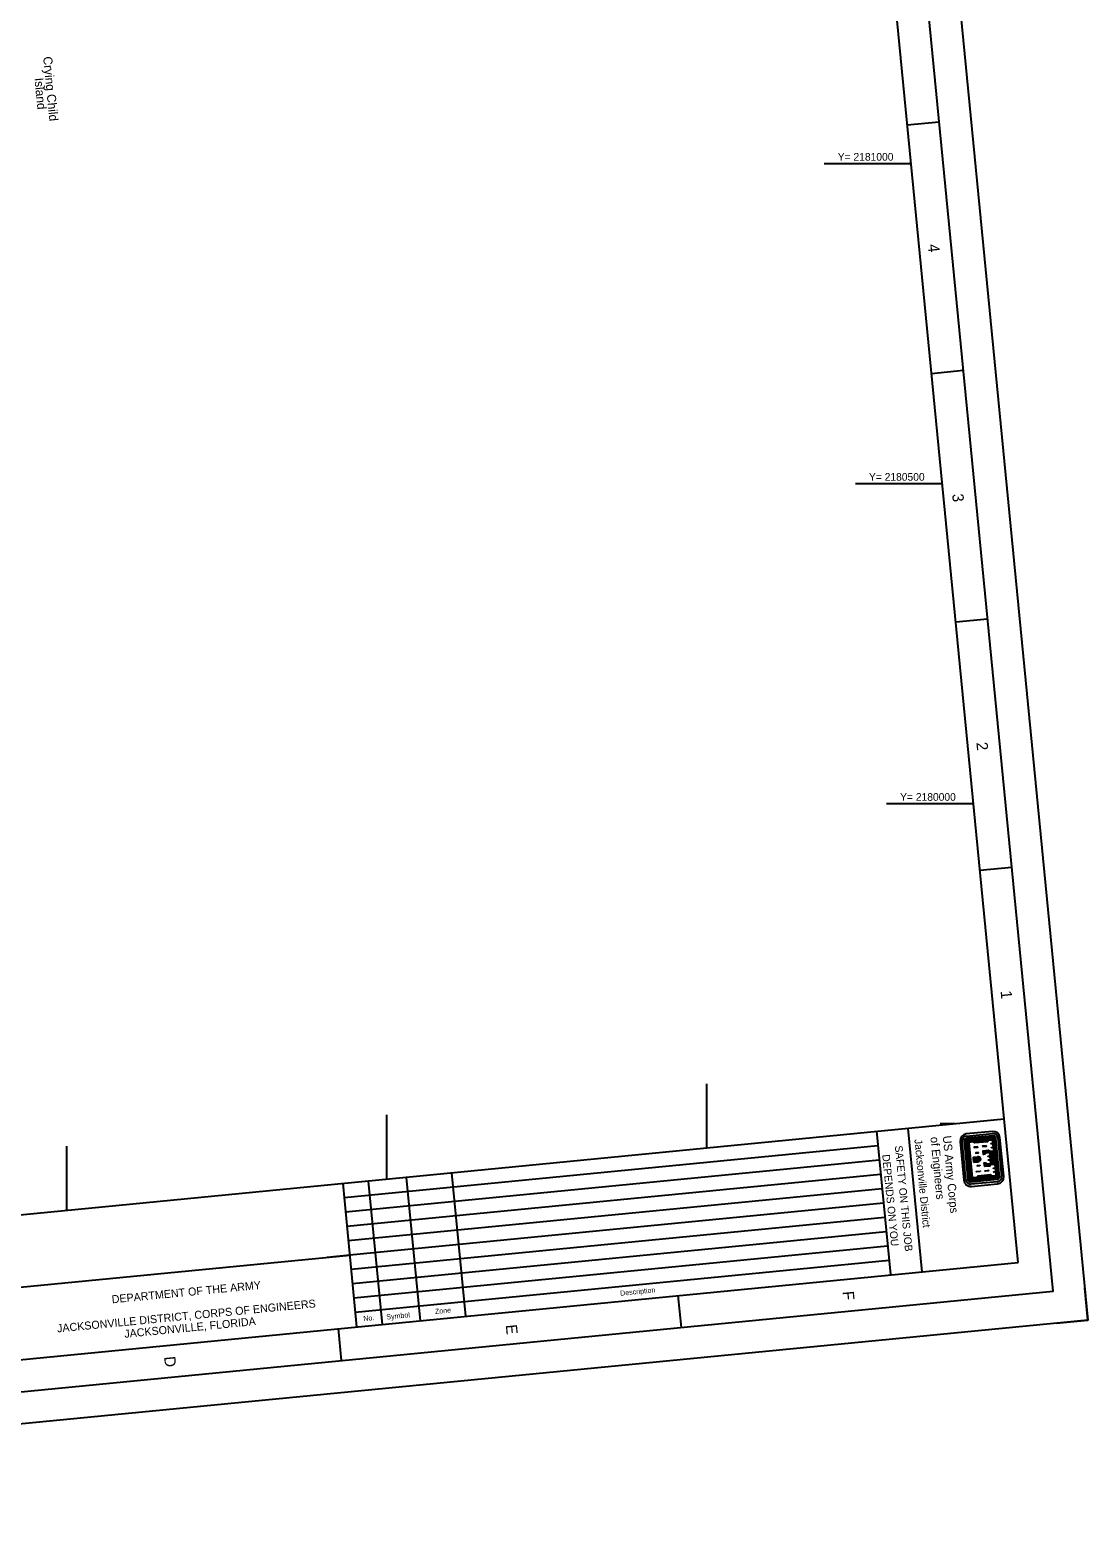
# Model space of a CAD drawing. Extents: x 516285 to 520096, y 2178864 to 2183573.
# Drawn here: x 518443 to 520096, y 2178864 to 2181209 of the extents above; entities that cross this region are included whole.
import ezdxf

# ---------------------------------------------------------------- set-up
doc = ezdxf.new("R2010")
doc.units = 0
for name, color, linetype in [('G-ANNO-NPLT', 7, 'Continuous'), ('G-ANNO-TEXT-LOGO', 7, 'Continuous'), ('G-ANNO-TEXT-TTLB', 7, 'Continuous'), ('G-ANNO-TTLB', 7, 'Continuous'), ('V-SITE-IDEN', 7, 'Continuous'), ('V-TOPO-COOR-STAT', 7, 'Continuous')]:
    doc.layers.add(name, color=color, linetype=linetype)

msp = doc.modelspace()

# ---------------------------------------------------------------- linework, layer by layer
at = {"layer": 'G-ANNO-NPLT'}
msp.add_lwpolyline([(519669, 2183572.9), (520095.6, 2179193.6), (516711.7, 2178864), (516285.1, 2183243.3)], close=True, dxfattribs=at)
msp.add_lwpolyline([(520045.9, 2179188.8), (520095.6, 2179193.6), (520090.8, 2179243.4)], dxfattribs=at)
at = {"layer": 'G-ANNO-TEXT-LOGO'}
for p, q in [((519895.8, 2179472.5), (519901.6, 2179412)), ((519904.9, 2179412.3), (519899, 2179472.8)), ((519908.4, 2179412.7), (519902.5, 2179473.2)), ((519909.2, 2179412.7), (519903.3, 2179473.3)), ((519910.1, 2179412.8), (519904.2, 2179473.3)), ((519911, 2179412.9), (519905.1, 2179473.4)), ((519946.3, 2179488.2), (519905.5, 2179484.2)), ((519905.8, 2179481), (519946.6, 2179485)), ((519911.8, 2179413), (519905.9, 2179473.5)), ((519946.9, 2179481.5), (519906.1, 2179477.6)), ((519947, 2179480.6), (519906.2, 2179476.7)), ((519947.1, 2179479.8), (519906.3, 2179475.9)), ((519947.2, 2179478.9), (519906.4, 2179475)), ((519947.3, 2179478), (519906.5, 2179474.1)), ((519947.3, 2179477.1), (519906.8, 2179473.2)), ((519912.7, 2179413.5), (519906.8, 2179473.2)), ((519947.4, 2179476.4), (519907.8, 2179472.5)), ((519913.5, 2179414.4), (519907.8, 2179472.5)), ((519938.8, 2179474.8), (519917.9, 2179472.8)), ((519938, 2179473.8), (519919, 2179472)), ((519953.8, 2179417.1), (519947.9, 2179477.6)), ((519954.7, 2179417.2), (519948.8, 2179477.7)), ((519955.5, 2179417.3), (519949.6, 2179477.8)), ((519956.4, 2179417.3), (519950.5, 2179477.9)), ((519957.3, 2179417.4), (519951.4, 2179477.9)), ((519954.8, 2179478.3), (519960.7, 2179417.8)), ((519963.9, 2179418.1), (519958, 2179478.6)), ((519916.1, 2179448), (519922.8, 2179448.6)), ((519916.1, 2179448), (519916.9, 2179440)), ((519916.2, 2179447.2), (519922.9, 2179447.8)), ((519916.3, 2179446.3), (519923, 2179446.9)), ((519944, 2179456), (519945.8, 2179437.5)), ((519944.9, 2179456.1), (519946.7, 2179437.6)), ((519945.7, 2179456.2), (519947.5, 2179437.7)), ((519946.6, 2179456.3), (519948.4, 2179437.8)), ((519947.5, 2179456.4), (519949.3, 2179437.8)), ((519948.3, 2179456.4), (519950.1, 2179437.9)), ((519949.2, 2179456.5), (519951, 2179438)), ((519916.4, 2179445.4), (519923.1, 2179446)), ((519916.5, 2179444.6), (519923.1, 2179445.2)), ((519916.6, 2179443.4), (519923.2, 2179444.1)), ((519916.7, 2179442.6), (519923.3, 2179443.3)), ((519916.7, 2179441.7), (519923.4, 2179442.4)), ((519916.8, 2179440.8), (519923.5, 2179441.5)), ((519916.9, 2179440), (519923.6, 2179440.7)), ((519953.3, 2179416.5), (519912.4, 2179412.6)), ((519953.3, 2179415.6), (519912.5, 2179411.7)), ((519953.4, 2179414.8), (519912.6, 2179410.9)), ((519953.2, 2179417.4), (519912.7, 2179413.5)), ((519953.5, 2179413.9), (519912.7, 2179410)), ((519953.6, 2179413.1), (519912.8, 2179409.1)), ((519953.9, 2179409.7), (519913.1, 2179405.7)), ((519913.4, 2179402.4), (519954.2, 2179406.4)), ((519953.1, 2179418.2), (519913.5, 2179414.4)), ((519944.3, 2179418.1), (519923.6, 2179416.1)), ((519943.4, 2179418.9), (519924.4, 2179417))]:
    msp.add_line(p, q, dxfattribs=at)
for points in [[(519947.5, 2179475.7), (519939.6, 2179474.9), (519938.1, 2179473), (519919.1, 2179471.2), (519917.1, 2179472.7), (519908.5, 2179471.9), (519914, 2179415.1), (519922.7, 2179416), (519924.3, 2179417.9), (519943.3, 2179419.8), (519945.2, 2179418.2), (519953, 2179418.9), (519952.3, 2179426.4), (519951.7, 2179432.2), (519951.2, 2179437.5), (519943.3, 2179436.8), (519941.8, 2179434.7), (519934.9, 2179434), (519934.5, 2179438.2), (519935.2, 2179438.3), (519937.1, 2179436.7), (519944.9, 2179437.4), (519944.2, 2179444.9), (519943.6, 2179450.7), (519943.1, 2179455.9), (519935.3, 2179455.2), (519933.7, 2179453.2), (519933, 2179453.1), (519932.6, 2179457.3), (519939.6, 2179458), (519941.4, 2179456.4), (519949.3, 2179457.1), (519948.6, 2179464.6), (519948, 2179470.4), (519947.5, 2179475.7)], [(519946.7, 2179474.8), (519940.1, 2179474.1), (519938.5, 2179472.2), (519918.8, 2179470.2), (519916.8, 2179471.9), (519909.5, 2179471.1), (519914.8, 2179416), (519922.2, 2179416.7), (519923.8, 2179418.8), (519943.5, 2179420.7), (519945.5, 2179419), (519952, 2179419.6), (519951.5, 2179425), (519948.4, 2179424.7), (519948.4, 2179425.2), (519951.5, 2179425.5), (519951, 2179430.8), (519947.9, 2179430.5), (519947.8, 2179430.9), (519950.9, 2179431.2), (519950.4, 2179436.6), (519943.8, 2179435.9), (519942.2, 2179433.9), (519934.2, 2179433.2), (519933.6, 2179438.9), (519935.5, 2179439.1), (519937.4, 2179437.5), (519944, 2179438.1), (519943.5, 2179443.5), (519940.4, 2179443.2), (519940.4, 2179443.6), (519943.5, 2179443.9), (519942.9, 2179449.3), (519939.8, 2179449), (519939.8, 2179449.5), (519942.9, 2179449.8), (519942.4, 2179455.1), (519935.8, 2179454.4), (519934.2, 2179452.5), (519932.3, 2179452.3), (519931.7, 2179458), (519939.8, 2179458.8), (519941.8, 2179457.2), (519948.3, 2179457.9), (519947.8, 2179463.1), (519944.7, 2179462.8), (519944.7, 2179463.3), (519947.8, 2179463.6), (519947.2, 2179469), (519944.2, 2179468.7), (519944.1, 2179469.1), (519947.2, 2179469.4), (519946.7, 2179474.8)], [(519923.6, 2179464.3), (519917.7, 2179463.7), (519917.8, 2179463.1), (519923.6, 2179463.7), (519923.6, 2179464.3)], [(519924.5, 2179455.1), (519920.4, 2179454.7), (519920.4, 2179454.2), (519924.5, 2179454.6), (519924.5, 2179455.1)], [(519936.8, 2179465.6), (519931, 2179465), (519931.1, 2179464.4), (519936.9, 2179465), (519936.8, 2179465.6)], [(519939.8, 2179456.6), (519939.3, 2179457.1), (519933.6, 2179456.5), (519933.8, 2179454.6), (519934.9, 2179456), (519939.9, 2179456.5)], [(519927.4, 2179425.6), (519921.5, 2179425), (519921.4, 2179425.5), (519927.3, 2179426.1), (519927.4, 2179425.6)], [(519926.5, 2179434.6), (519922.4, 2179434.2), (519922.3, 2179434.7), (519926.4, 2179435.1), (519926.5, 2179434.6)], [(519940.6, 2179426.9), (519934.8, 2179426.3), (519934.8, 2179426.8), (519940.5, 2179427.4), (519940.6, 2179426.9)], [(519941.8, 2179436.1), (519941.4, 2179435.6), (519935.7, 2179435), (519935.5, 2179436.8), (519936.9, 2179435.7), (519941.9, 2179436.2)]]:
    msp.add_lwpolyline(points, dxfattribs=at)
for centre, major_axis, start_param, end_param in [((519906.5, 2179473.5), (-1, 10.7), 6.28317, 7.853966), ((519906.5, 2179473.5), (-0.73, 7.45), 6.28317, 7.853966), ((519906.5, 2179473.5), (-0.39, 4), 6.28317, 7.853966), ((519906.5, 2179473.5), (-0.31, 3.13), 6.28317, 7.853966), ((519906.5, 2179473.5), (-0.22, 2.27), 6.28317, 7.853966), ((519906.5, 2179473.5), (-0.14, 1.41), 6.28317, 7.853966), ((519906.5, 2179473.5), (-0.053, 0.543), 6.28317, 7.853966), ((519947.3, 2179477.5), (1, -10.7), 1.57078, 3.141576), ((519947.3, 2179477.5), (0.73, -7.45), 1.57078, 3.141576), ((519947.3, 2179477.5), (0.39, -4), 1.57078, 3.141576), ((519947.3, 2179477.5), (0.31, -3.13), 1.57078, 3.141576), ((519947.3, 2179477.5), (0.22, -2.27), 1.57078, 3.141576), ((519947.3, 2179477.5), (0.14, -1.41), 1.57078, 3.141576), ((519947.3, 2179477.5), (0.053, -0.543), 1.57078, 3.141576), ((519922.9, 2179443.1), (-0.54, 5.53), 4.985832, 6.214359), ((519922.9, 2179443.1), (-0.45, 4.66), 4.947465, 6.21436), ((519922.9, 2179443.1), (-0.37, 3.8), 4.947465, 6.21436), ((519922.9, 2179443.1), (-0.29, 2.94), 4.947465, 6.21436), ((519922.9, 2179443.1), (-0.2, 2.07), 4.947465, 6.214359), ((519922.6, 2179446.1), (0.2, -2.07), 0.068794, 1.335689), ((519922.6, 2179446.1), (0.29, -2.94), 0.068794, 1.335689), ((519922.6, 2179446.1), (0.37, -3.8), 0.068795, 1.335689), ((519922.6, 2179446.1), (0.45, -4.66), 0.068795, 1.335689), ((519922.6, 2179446.1), (0.54, -5.53), 0.068795, 1.29842), ((519912.4, 2179413.1), (1, -10.7), 4.712373, 6.28317), ((519912.4, 2179413.1), (-0.73, 7.45), 1.570781, 3.141577), ((519912.4, 2179413.1), (0.39, -4), 4.712373, 6.28317), ((519912.4, 2179413.1), (0.31, -3.13), 4.712373, 6.28317), ((519912.4, 2179413.1), (0.22, -2.27), 4.712373, 6.28317), ((519912.4, 2179413.1), (0.14, -1.41), 4.712373, 6.28317), ((519912.4, 2179413.1), (0.053, -0.543), 4.712373, 6.28317), ((519953.2, 2179417.1), (0.053, -0.543), 6.283169, 7.853965), ((519953.2, 2179417.1), (0.22, -2.27), 6.283169, 7.853965), ((519953.2, 2179417.1), (0.14, -1.41), 6.283169, 7.853965), ((519953.2, 2179417.1), (0.31, -3.13), 6.283169, 7.853965), ((519953.2, 2179417.1), (0.39, -4), 6.283169, 7.853965), ((519953.2, 2179417.1), (0.73, -7.45), 6.28317, 7.853966), ((519953.2, 2179417.1), (1, -10.7), 6.283169, 7.853965)]:
    msp.add_ellipse(centre, major_axis=major_axis, ratio=0.99964, start_param=start_param, end_param=end_param, dxfattribs=at)
at = {"layer": 'G-ANNO-TTLB'}
for p, q in [((519863.1, 2181064.9), (519813.3, 2181060.1)), ((519900.9, 2180676.7), (519851.2, 2180671.9)), ((519938.7, 2180288.6), (519889, 2180283.7)), ((519976.5, 2179900.4), (519926.8, 2179895.6)), ((519964.6, 2179507.4), (516779.7, 2179197.2)), ((519765.1, 2179488.6), (519786.9, 2179264.7)), ((519814.1, 2179492.8), (519835.9, 2179268.8)), ((519767.3, 2179465.8), (518933.4, 2179384.6)), ((519769.5, 2179443.4), (518935.6, 2179362.2)), ((519101.4, 2179423.3), (519123.2, 2179199.4)), ((518931.2, 2179406.8), (518953, 2179182.8)), ((519771.7, 2179421), (518937.7, 2179339.8)), ((518970.9, 2179410.6), (518992.6, 2179186.7)), ((519030.6, 2179416.4), (519052.4, 2179192.5)), ((519773.9, 2179398.6), (518939.9, 2179317.4)), ((519776.1, 2179376.2), (518942.1, 2179295)), ((519778.2, 2179353.8), (518944.3, 2179272.6)), ((519780.4, 2179331.4), (518946.5, 2179250.2)), ((519782.6, 2179309), (518948.6, 2179227.8)), ((518086.5, 2179212.1), (518942.1, 2179294.8)), ((518942.1, 2179294.8), (518906.9, 2179291.4)), ((519784.8, 2179286.6), (518950.8, 2179205.4)), ((519460.3, 2179182), (519455.4, 2179231.8)), ((518929.5, 2179130.3), (518924.6, 2179180.1))]:
    msp.add_line(p, q, dxfattribs=at)
for points in [[(516339.7, 2183198.4), (516756.6, 2178918.6), (520041, 2179238.6), (519624.1, 2183518.3)], [(519986.4, 2179283.5), (519586.5, 2183389), (516401.6, 2183078.8), (516801.5, 2178973.2)]]:
    msp.add_lwpolyline(points, close=True, dxfattribs=at)
at = {"layer": 'V-TOPO-COOR-STAT'}
for p, q in [((519819.2, 2181000), (519683.6, 2181000)), ((519867.9, 2180500), (519732.3, 2180500)), ((519916.6, 2180000), (519781, 2180000)), ((519500, 2179462.2), (519500, 2179562.7)), ((519000, 2179413.5), (519000, 2179514)), ((519888.1, 2179500), (519864.8, 2179500)), ((518500, 2179364.8), (518500, 2179465.3))]:
    msp.add_line(p, q, dxfattribs=at)

# ---------------------------------------------------------------- texts
at = {"layer": 'G-ANNO-TEXT-TTLB'}
for s, height, rotation, p in [('Jacksonville District', 11.9, 275.5635, (519824.3, 2179475.7)), ('of Engineers', 13.086, 275.5635, (519849.4, 2179479.2)), ('US Army Corps', 13.086, 275.5635, (519868.7, 2179481)), ('DEPENDS ON YOU', 11.9, 275.5635, (519774.1, 2179451.8)), ('SAFETY ON THIS JOB', 11.9, 275.5635, (519793.8, 2179465.6)), ('DEPARTMENT OF THE ARMY', 12.5, 5.5635, (518570.9, 2179219.6)), ('Description', 8, 5.5635, (519365, 2179231.4)), ('JACKSONVILLE DISTRICT, CORPS OF ENGINEERS', 12.5, 5.5635, (518485.5, 2179174.1)), ('JACKSONVILLE, FLORIDA', 12.5, 5.5635, (518590.6, 2179165.7)), ('No.', 8, 5.5635, (518963.8, 2179191.8)), ('Symbol', 8, 5.5635, (518999.8, 2179194.3)), ('Zone', 8, 5.5635, (519075.7, 2179202.9))]:
    msp.add_text(s, height=height, rotation=rotation, dxfattribs=at).set_placement(p)
at = {"layer": 'G-ANNO-TTLB'}
for s, p in [('4', (519845.4, 2180873.6)), ('3', (519883.4, 2180483.7)), ('2', (519921.2, 2180095.5)), ('1', (519959, 2179707.4)), ('F', (519712.2, 2179237.9)), ('E', (519185.9, 2179185.8)), ('D', (518652.1, 2179136.1))]:
    msp.add_text(s, height=17.5, rotation=275.5635, dxfattribs=at).set_placement(p)
at = {"layer": 'V-SITE-IDEN'}
for s, p in [('Crying Child', (518463.1, 2181166.8)), ('Island', (518449.5, 2181133.5))]:
    msp.add_text(s, height=13.92, rotation=275.5635, dxfattribs=at).set_placement(p)
at = {"layer": 'V-TOPO-COOR-STAT'}
for s, p in [('Y= 2181000', (519704.7, 2181004.7)), ('Y= 2180500', (519753.4, 2180504.7)), ('Y= 2180000', (519802.1, 2180004.7))]:
    msp.add_text(s, height=12, dxfattribs=at).set_placement(p)

doc.saveas('drawing.dxf')
